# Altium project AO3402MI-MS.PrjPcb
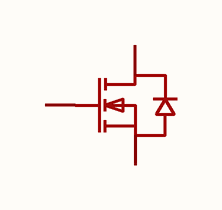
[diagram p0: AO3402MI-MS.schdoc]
1 sheet, 1 parts. Net scope: global (net labels, ports and power ports of the same name join across sheets).

## Sheet AO3402MI-MS.schdoc
size 127 x 101 mm

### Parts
Q?  ao3402mi-ms  [SOT-23-3L_L2.9-W1.6-P1.90-LS2.8-BL]  (value not drawn)

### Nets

Not connected (* = marked no-connect by the designer): Q? 1(G) 2(S) 3(D)

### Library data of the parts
Q? = ao3402mi-ms: 数量:1个N沟道;漏源电压(Vdss):30V;连续漏极电流(Id):4A;导通电阻(RDS(on)):47mΩ@4.5V;耗散功率(Pd):1.4W;阈值电压(Vgs(th)):900mV;; Manufacturer: MSKSEMI(美森科); AddInBom: yes; ModelId: 2d96a8b5277e418381ab33231166f920; ModelTransform: 114.96,110.236,0,0,0,0,-0.001,0.003,0; Number: 1个N沟道; Drain to Source Voltage: 30V; Current - Continuous Drain(Id): 4A; Pd - Power Dissipation: 1.4W; Gate Threshold Voltage (Vgs(th)): 900mV; Gate Charge(Qg): 8.4nC@4.5V; Input Capacitance(Ciss): 695pF; Reverse Transfer Capacitance (Crss@Vds): 36pF; Output Capacitance(Coss): 45pF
